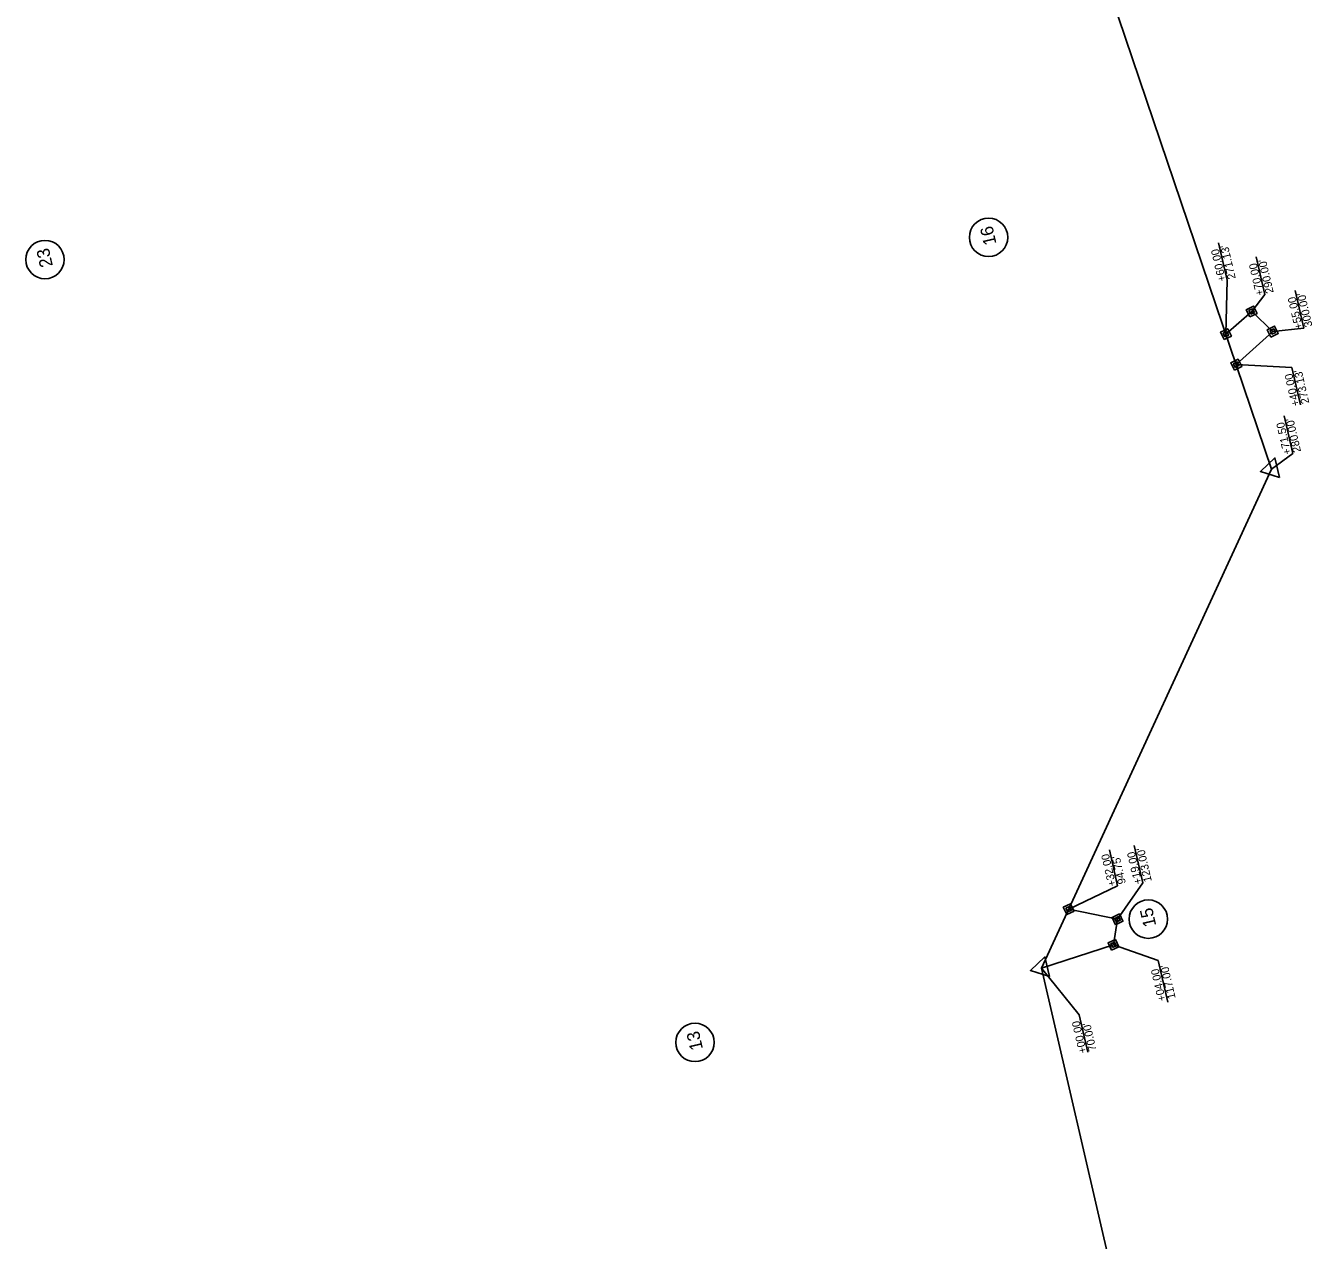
# Model space of a CAD drawing. Extents: x 474184 to 481900, y 489262 to 505659.
# Drawn here: x 480705 to 481509, y 492010 to 492769 of the extents above; entities that cross this region are included whole.
import ezdxf

# ---------------------------------------------------------------- set-up
doc = ezdxf.new("R2010")
doc.units = 0
for name, color, linetype in [('Prop Drainage Structure Outlet Berm Ditch 850 10 Label', 7, 'Continuous'), ('Prop Drainage Structure Pipe CSP 15in', 7, 'Continuous'), ('Prop Drainage Structure Pipe RCP 18in Class IV', 7, 'Continuous'), ('Prop Drainage Structure Pipe RCP 18in Class IV Label', 7, 'Continuous'), ('Prop Drainage Structure Pipe Side Drain 15in Label', 7, 'Continuous'), ('Prop Drainage Structure Plot Symbol 50 Scale', 7, 'Continuous'), ('Prop Earthen Structure Base Ditch Lateral Detail Label', 7, 'Continuous')]:
    doc.layers.add(name, color=color, linetype=linetype)

msp = doc.modelspace()

# ---------------------------------------------------------------- linework, layer by layer
at = {"layer": 'Prop Drainage Structure Outlet Berm Ditch 850 10 Label'}
for p, q in [((481455.13, 492576.42), (481471.24, 492590.54)), ((481484.39, 492578.04), (481471.24, 492590.54)), ((481461.57, 492557.38), (481484.39, 492578.04)), ((481387.39, 492210.86), (481356.94, 492217.19)), ((481384.91, 492194.9), (481387.39, 492210.86)), ((481384.91, 492194.9), (481340.01, 492180.44))]:
    msp.add_line(p, q, dxfattribs=at)
at = {"layer": 'Prop Drainage Structure Pipe CSP 15in'}
for p, q in [((481306.87, 492636.9), (481306.87, 492636.9)), ((480717.48, 492623.03), (480717.48, 492623.03)), ((481406.67, 492210.98), (481406.67, 492210.98)), ((481123.53, 492133.95), (481123.53, 492133.95))]:
    msp.add_line(p, q, dxfattribs=at)
for centre in [(481306.87, 492636.9), (480717.48, 492623.03), (481406.67, 492210.98), (481123.53, 492133.95)]:
    msp.add_circle(centre, 12, dxfattribs=at)
at = {"layer": 'Prop Drainage Structure Pipe RCP 18in Class IV'}
for p, q in [((481471.24, 492590.54), (481471.24, 492590.54)), ((481455.13, 492576.42), (481455.13, 492576.42)), ((481484.39, 492578.04), (481484.39, 492578.04)), ((481461.57, 492557.38), (481461.57, 492557.38)), ((481483.65, 492492.18), (481483.65, 492492.18)), ((481356.94, 492217.19), (481356.94, 492217.19)), ((481387.39, 492210.86), (481387.39, 492210.86)), ((481384.91, 492194.9), (481384.91, 492194.9)), ((481340.01, 492180.44), (481340.01, 492180.44))]:
    msp.add_line(p, q, dxfattribs=at)
for points in [[(481488.57, 492486.9), (481476.64, 492490.56), (481485.76, 492499.08)], [(481344.92, 492175.16), (481332.99, 492178.83), (481342.11, 492187.34)]]:
    msp.add_lwpolyline(points, close=True, dxfattribs=at)
at = {"layer": 'Prop Drainage Structure Pipe RCP 18in Class IV Label'}
for points in [[(481470.07, 492587.14), (481467.84, 492591.71), (481472.41, 492593.94), (481474.65, 492589.37)], [(481470.66, 492588.84), (481469.54, 492591.13), (481471.83, 492592.24), (481472.94, 492589.96)], [(481453.96, 492573.02), (481451.72, 492577.6), (481456.3, 492579.83), (481458.53, 492575.25)], [(481454.54, 492574.72), (481453.43, 492577.01), (481455.71, 492578.12), (481456.83, 492575.84)], [(481483.22, 492574.63), (481480.98, 492579.21), (481485.56, 492581.44), (481487.79, 492576.87)], [(481483.8, 492576.34), (481482.69, 492578.62), (481484.97, 492579.74), (481486.09, 492577.45)], [(481460.4, 492553.98), (481458.17, 492558.56), (481462.75, 492560.79), (481464.98, 492556.21)], [(481460.99, 492555.68), (481459.87, 492557.97), (481462.16, 492559.09), (481463.28, 492556.8)], [(481355.77, 492213.78), (481353.54, 492218.36), (481358.11, 492220.59), (481360.34, 492216.01)], [(481356.35, 492215.48), (481355.24, 492217.77), (481357.53, 492218.89), (481358.64, 492216.6)], [(481386.21, 492207.46), (481383.98, 492212.04), (481388.56, 492214.27), (481390.79, 492209.69)], [(481386.8, 492209.16), (481385.68, 492211.45), (481387.97, 492212.57), (481389.09, 492210.28)], [(481383.74, 492191.5), (481381.51, 492196.07), (481386.08, 492198.3), (481388.31, 492193.73)], [(481384.32, 492193.2), (481383.21, 492195.49), (481385.5, 492196.6), (481386.61, 492194.31)]]:
    msp.add_lwpolyline(points, close=True, dxfattribs=at)
at = {"layer": 'Prop Drainage Structure Pipe Side Drain 15in Label'}
for p, q in [((481483.65, 492492.18), (481367.49, 492835.24)), ((481340.01, 492180.44), (481483.65, 492492.18)), ((481435.48, 491766.31), (481340.01, 492180.44))]:
    msp.add_line(p, q, dxfattribs=at)
at = {"layer": 'Prop Drainage Structure Plot Symbol 50 Scale'}
for p, q in [((481491.51, 492525.36), (481496.91, 492501.93)), ((481363.38, 492151.28), (481368.78, 492127.85))]:
    msp.add_line(p, q, dxfattribs=at)
for points in [[(481496.91, 492501.93), (481483.65, 492492.18)], [(481363.38, 492151.28), (481340.01, 492180.44)]]:
    msp.add_lwpolyline(points, dxfattribs=at)
at = {"layer": 'Prop Earthen Structure Base Ditch Lateral Detail Label'}
for p, q in [((481450.41, 492633.49), (481455.81, 492610.06)), ((481474.12, 492624.64), (481479.52, 492601.21)), ((481498.38, 492603.64), (481503.78, 492580.21)), ((481496.37, 492555.63), (481501.78, 492532.2)), ((481387.51, 492231.83), (481382.35, 492254.21)), ((481403.22, 492233.62), (481397.82, 492257.05)), ((481356.94, 492217.19), (481387.51, 492231.83)), ((481387.39, 492210.86), (481403.22, 492233.62)), ((481384.91, 492194.9), (481412.77, 492185.23)), ((481412.77, 492185.23), (481418.78, 492159.16))]:
    msp.add_line(p, q, dxfattribs=at)
for points in [[(481455.81, 492610.06), (481455.13, 492576.42)], [(481479.52, 492601.21), (481471.24, 492590.54)], [(481503.78, 492580.21), (481484.39, 492578.04)], [(481496.37, 492555.63), (481461.57, 492557.38)]]:
    msp.add_lwpolyline(points, dxfattribs=at)

# ---------------------------------------------------------------- texts
at = {"layer": 'Prop Drainage Structure Pipe CSP 15in'}
for s, p in [('16', (481311.88, 492632.97)), ('23', (480722.49, 492619.13)), ('15', (481411.68, 492207.05)), ('13', (481128.54, 492130.02))]:
    msp.add_text(s, height=8, rotation=102.98112, dxfattribs=at).set_placement(p)
at = {"layer": 'Prop Drainage Structure Plot Symbol 50 Scale'}
for s, p in [('+71.50', (481496, 492501.72)), ("280.00'", (481502.09, 492503.13)), ('+00.00', (481368.27, 492127.73)), ("70.00'", (481374.36, 492129.14))]:
    msp.add_text(s, height=5, rotation=102.98112, dxfattribs=at).set_placement(p)
at = {"layer": 'Prop Earthen Structure Base Ditch Lateral Detail Label'}
for s, p in [("271.13'", (481461.29, 492611.32)), ('+60.00', (481455.2, 492609.92)), ('+70.00', (481478.91, 492601.07)), ("290.00'", (481485, 492602.47)), ('+55.00', (481503.17, 492580.07)), ("300.00'", (481509.26, 492581.47)), ('+40.00', (481501.17, 492532.06)), ("273.13'", (481507.26, 492533.47)), ("123.00' ", (481408.87, 492234.8)), ('+32.00', (481386.61, 492232.04)), ("94.75' ", (481392.7, 492233.44)), ('+19.00', (481402.78, 492233.4)), ("117.00' ", (481423.77, 492161.69)), ('+04.00', (481417.68, 492160.28))]:
    msp.add_text(s, height=5, rotation=102.98112, dxfattribs=at).set_placement(p)

doc.saveas('drawing.dxf')
